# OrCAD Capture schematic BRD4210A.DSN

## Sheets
1 WSTK Connectors & Board ID: size A3; title: xG23B 868-915 MHz 20 dBm Radio Board; rev: A00; company: Silicon Labs; note: BRD4210A
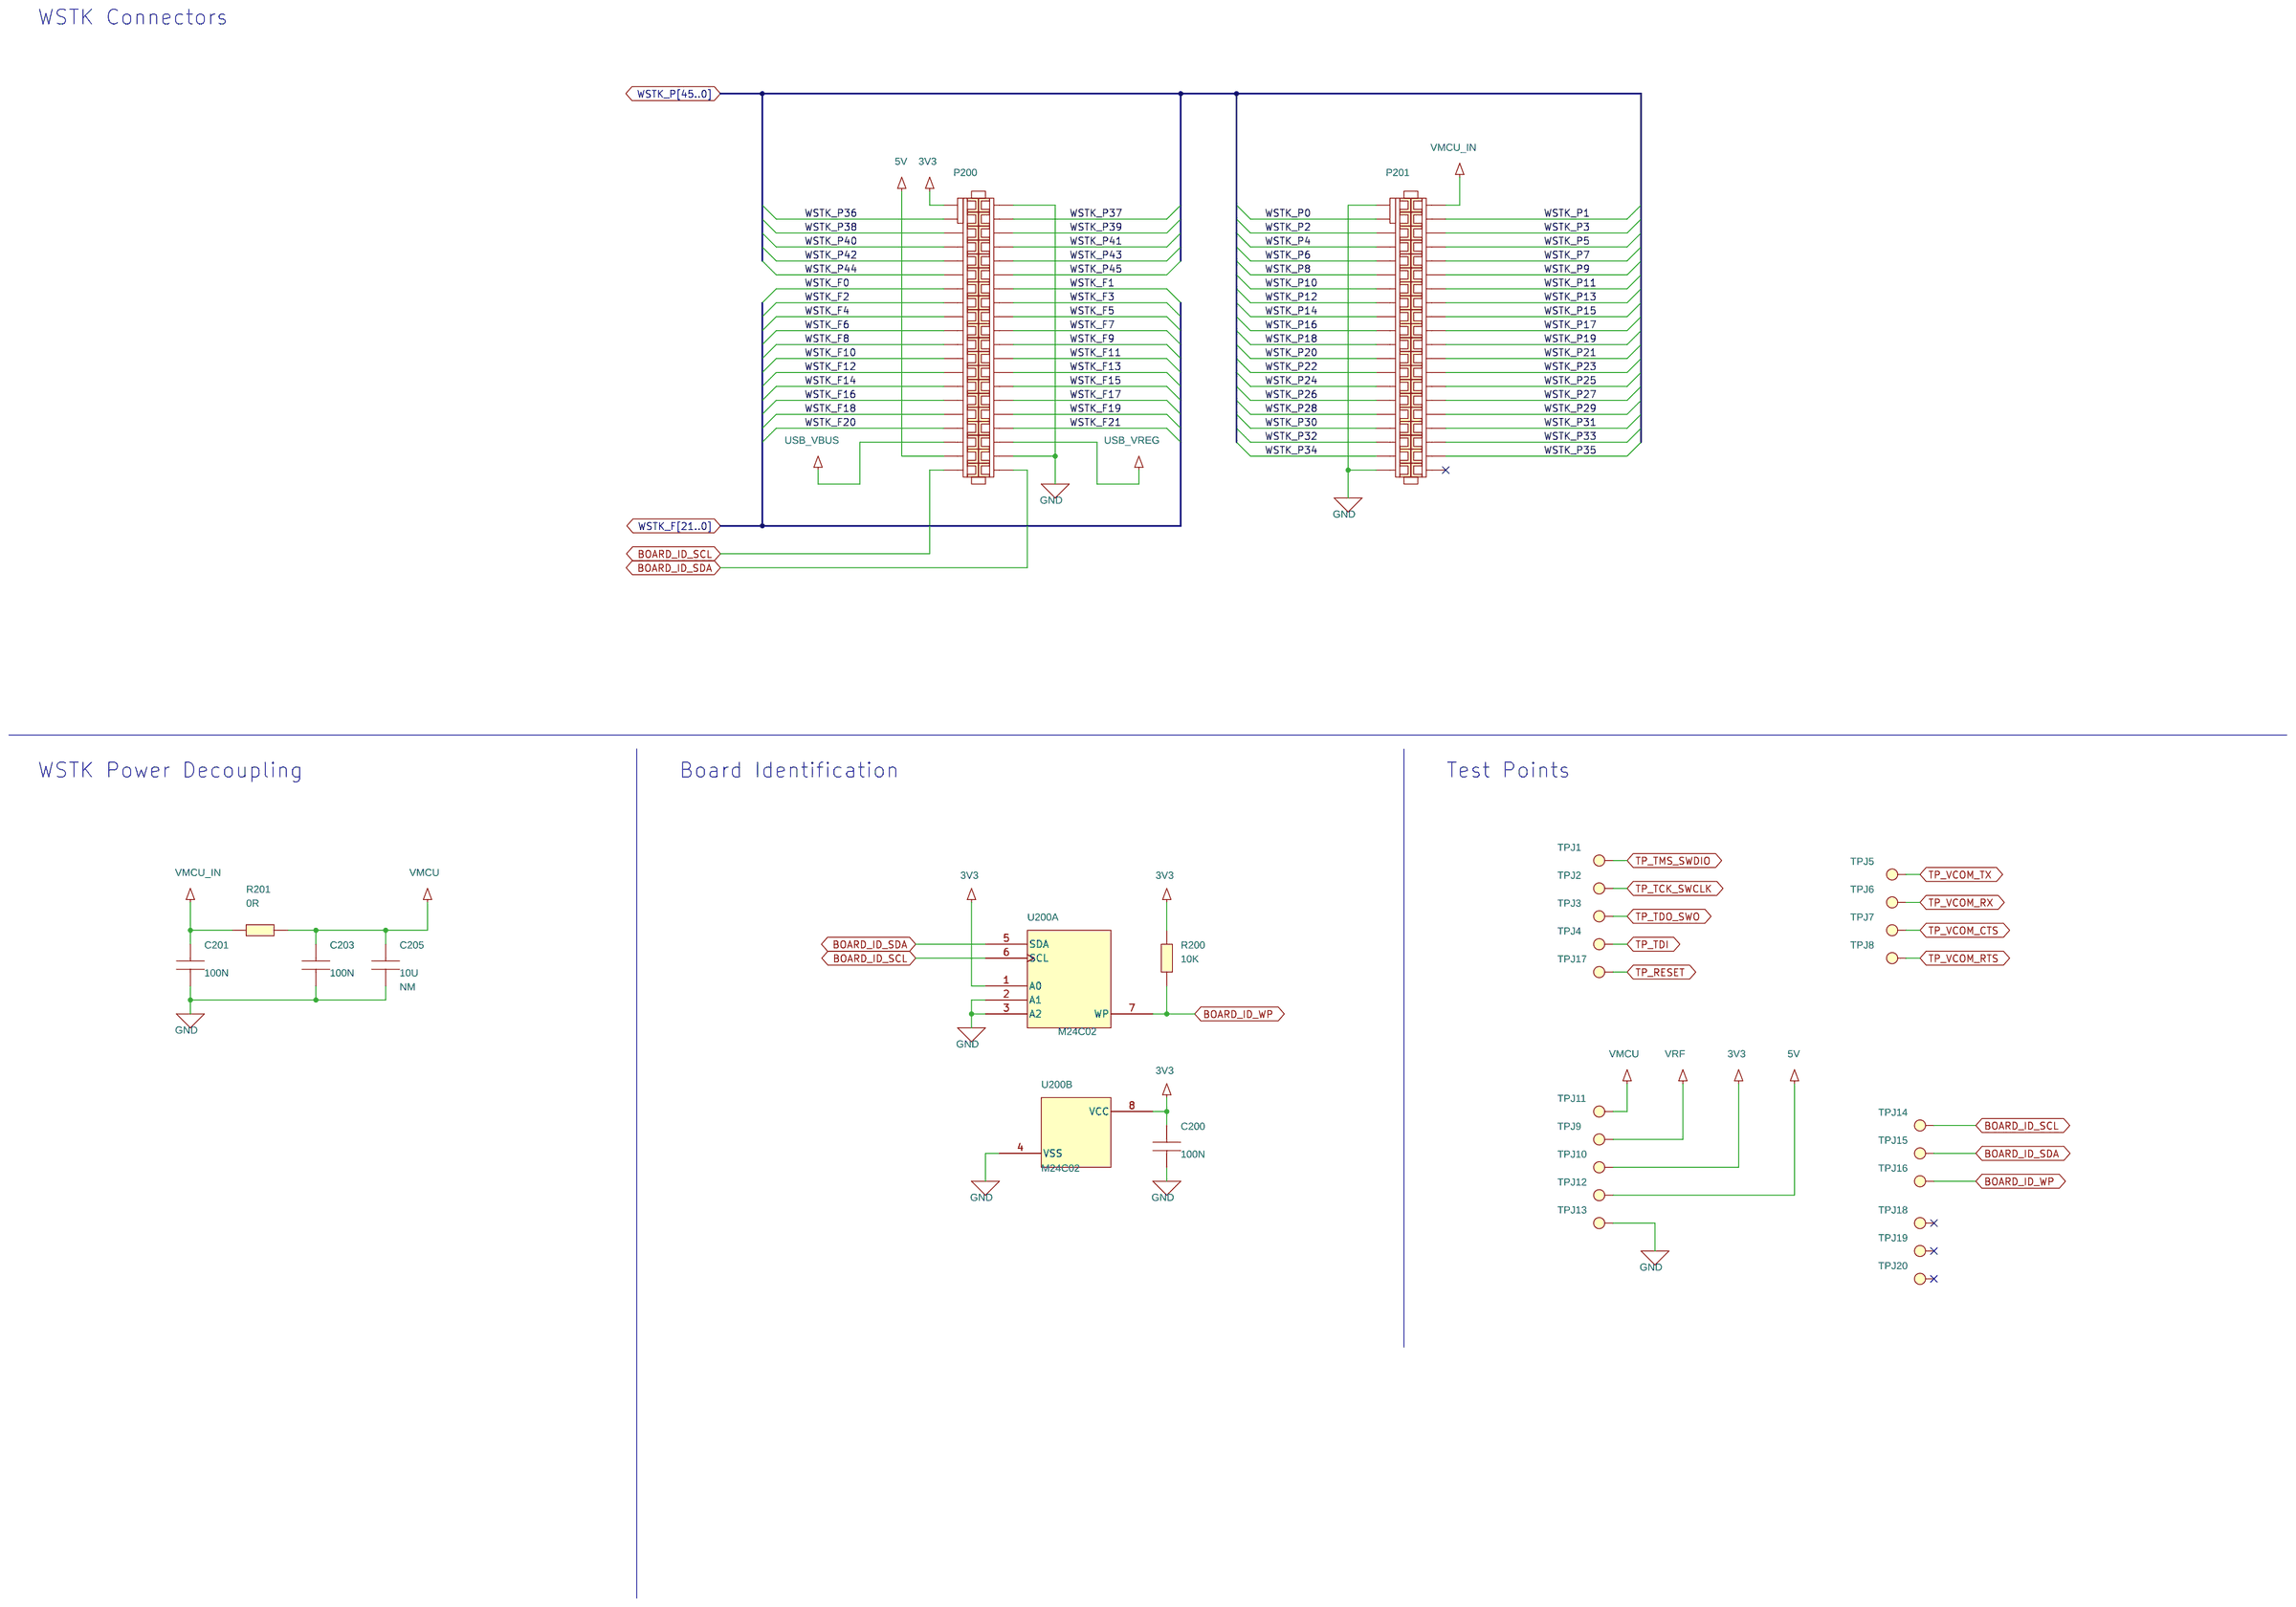
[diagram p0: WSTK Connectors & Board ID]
2 02: RF & Power: size A3
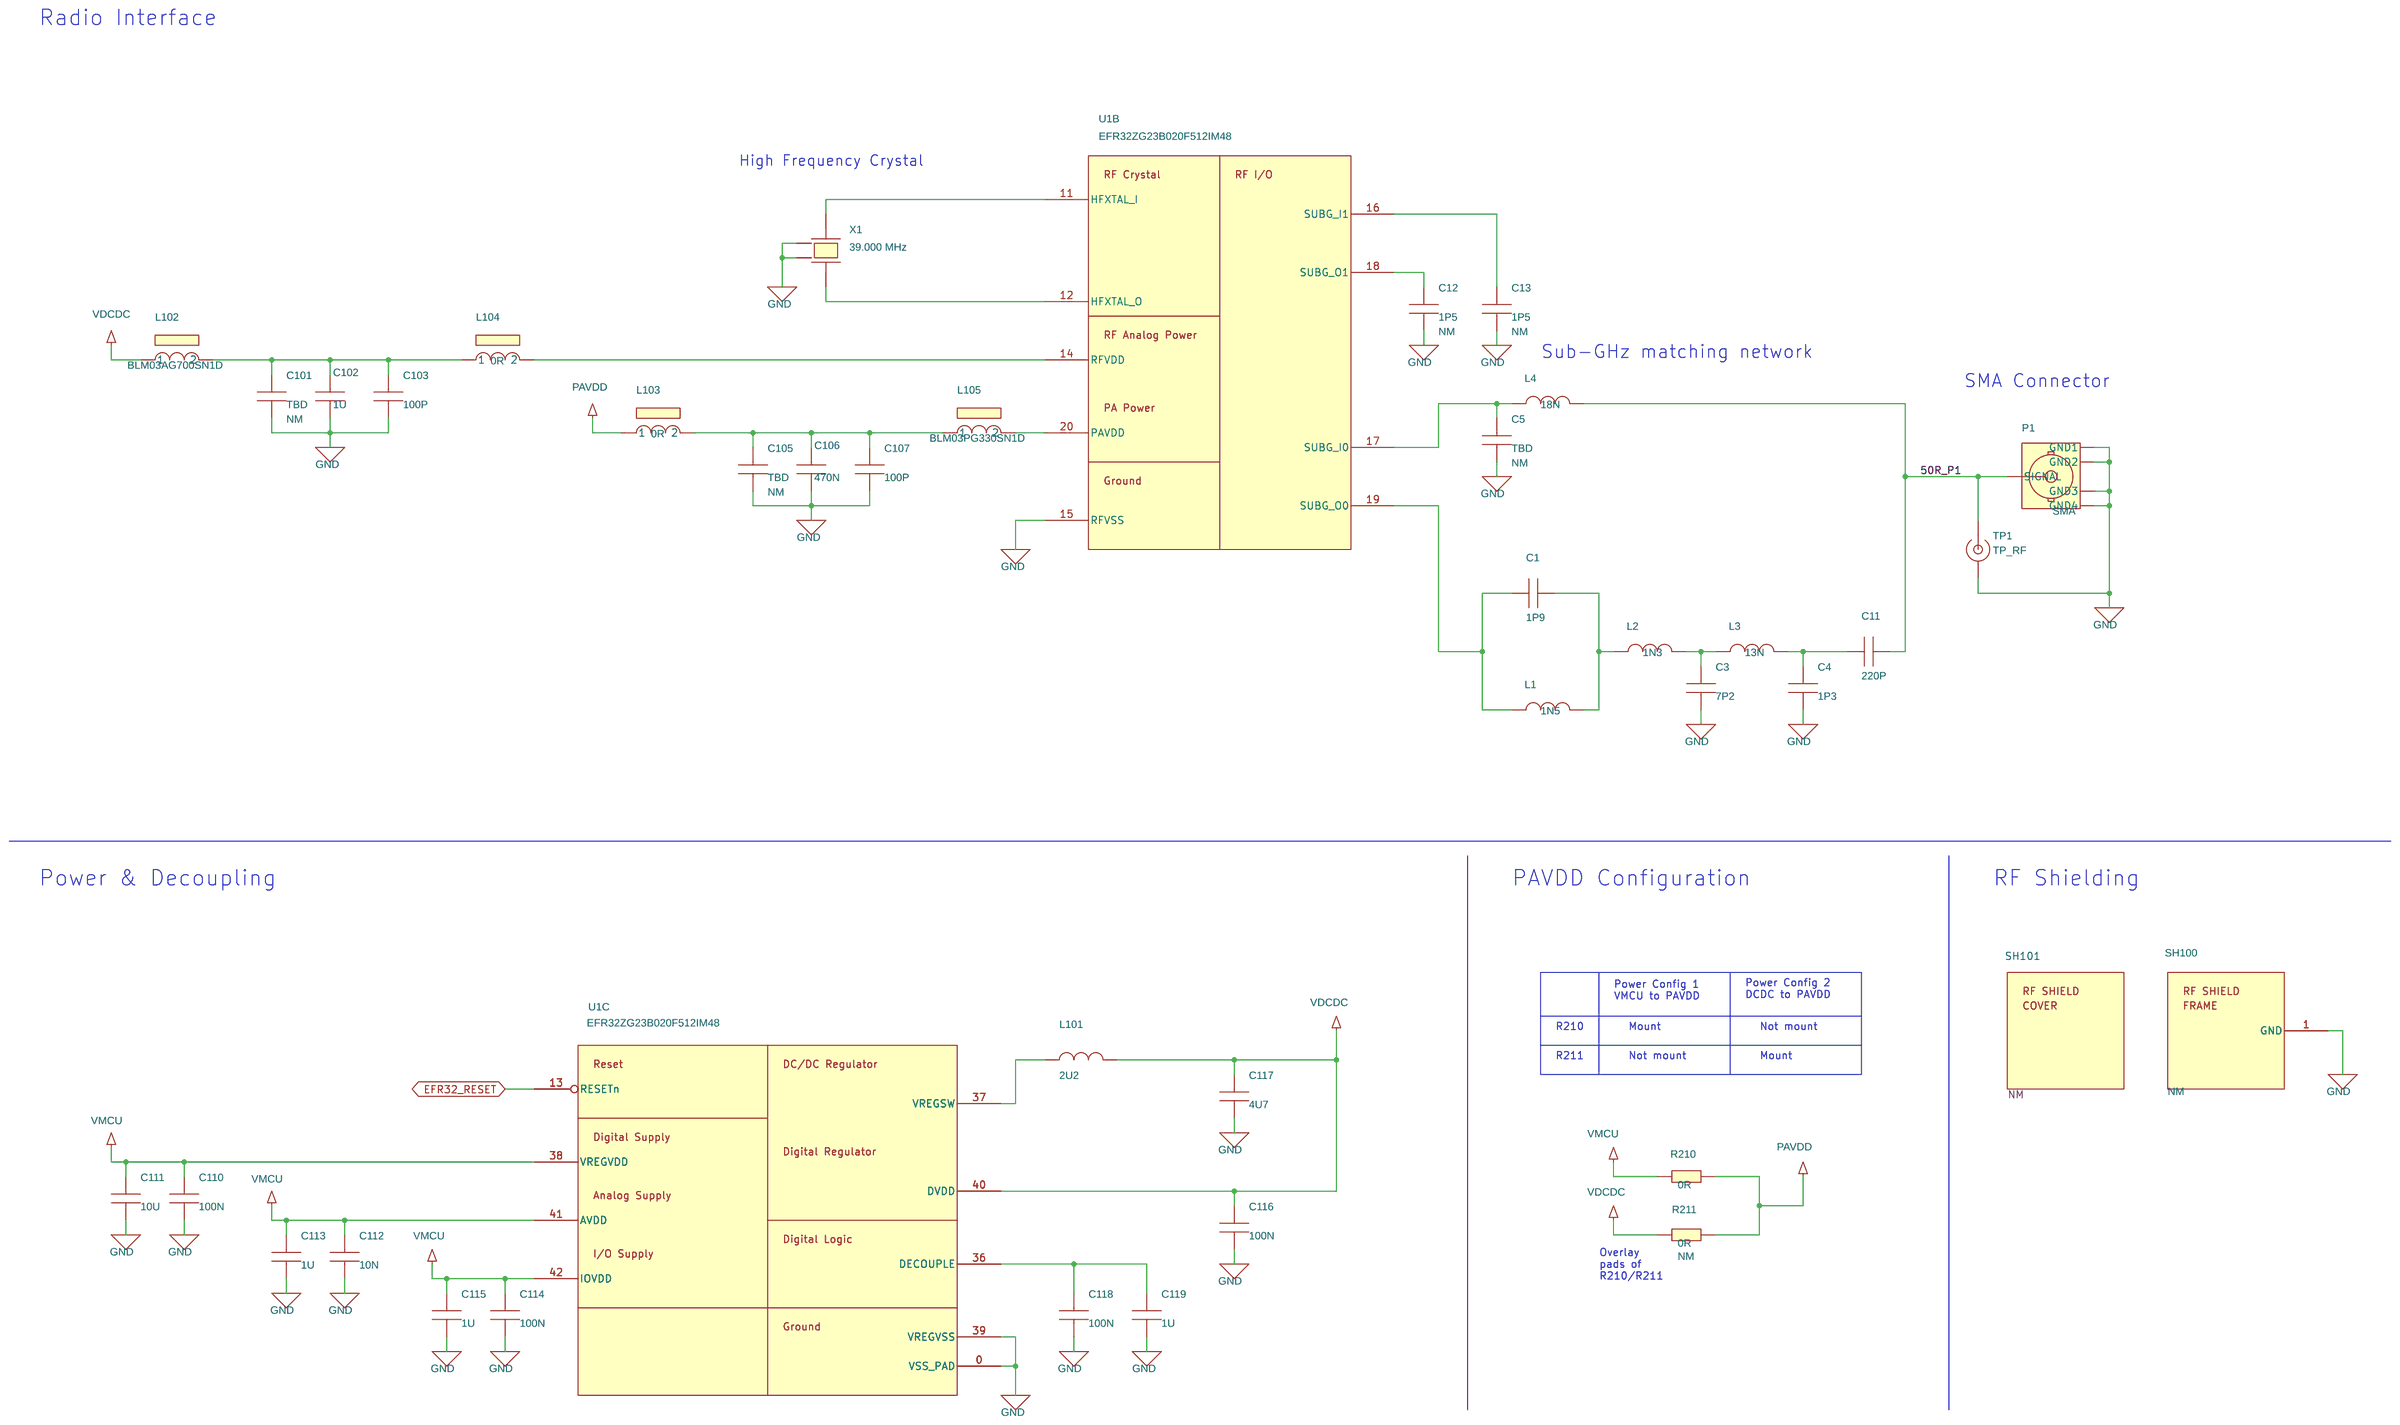
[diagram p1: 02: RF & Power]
3 01: Title Page
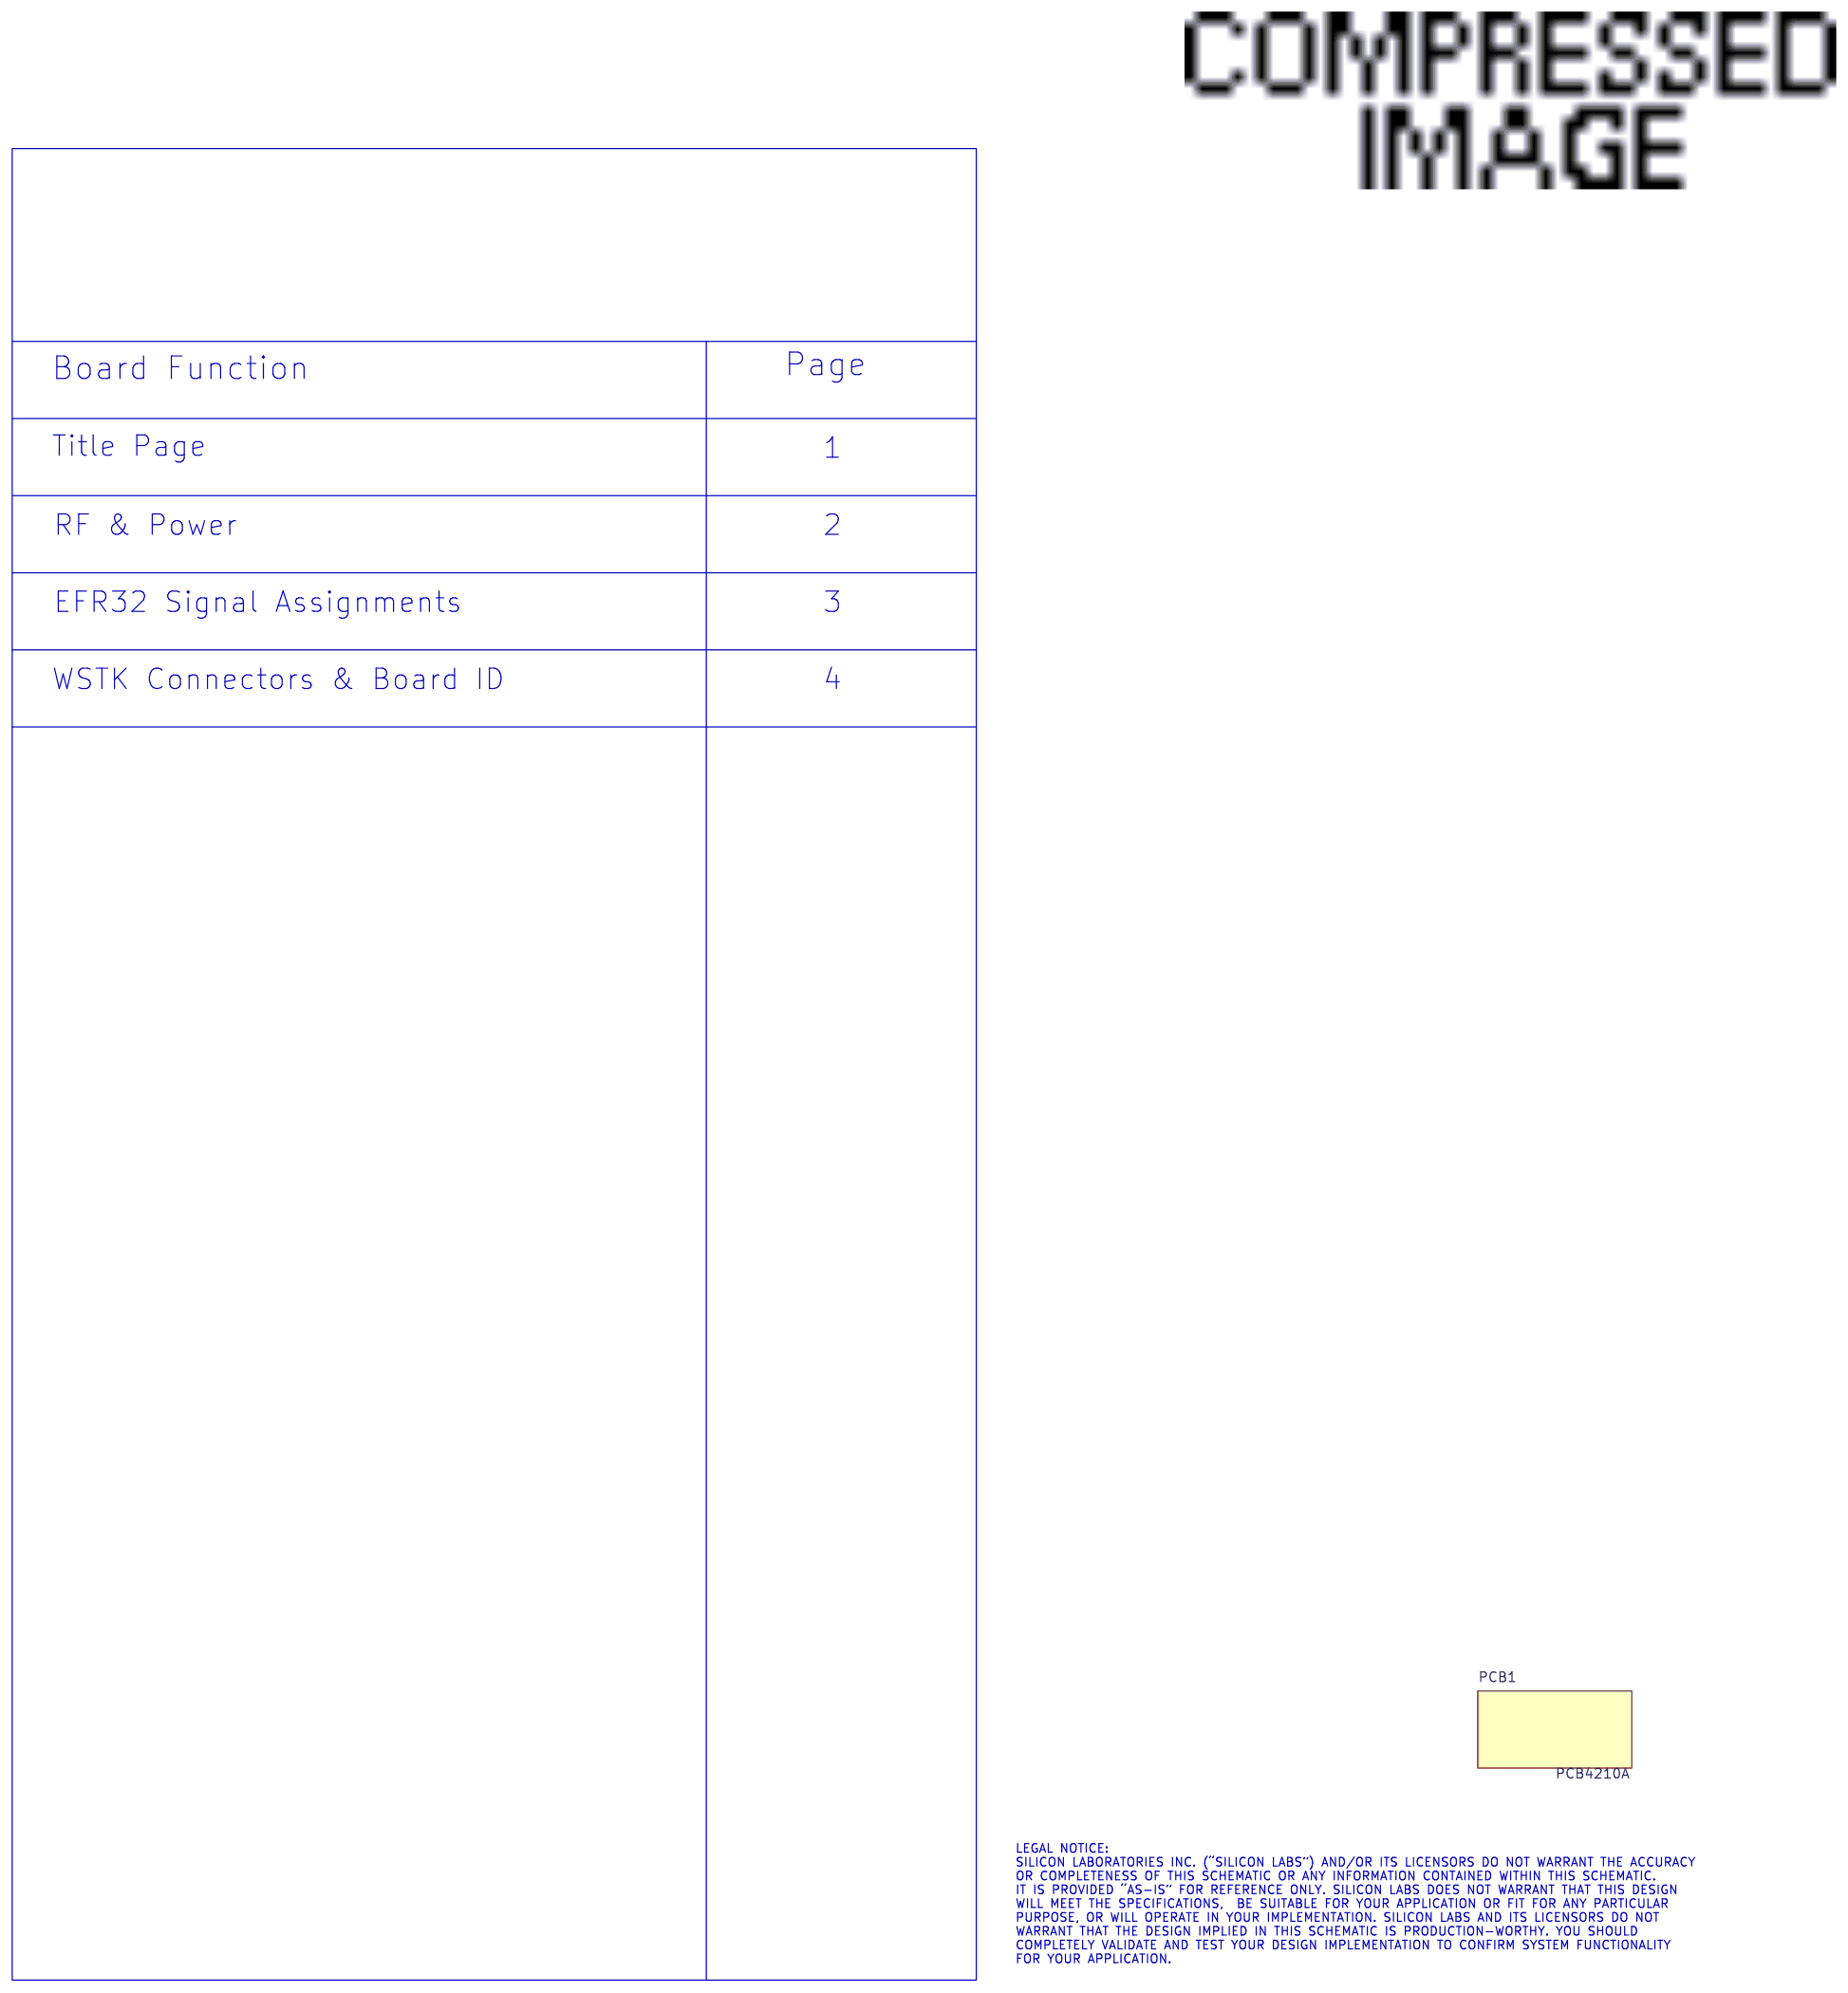
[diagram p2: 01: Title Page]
4 03: EFR32 Signal Assignments: size A3
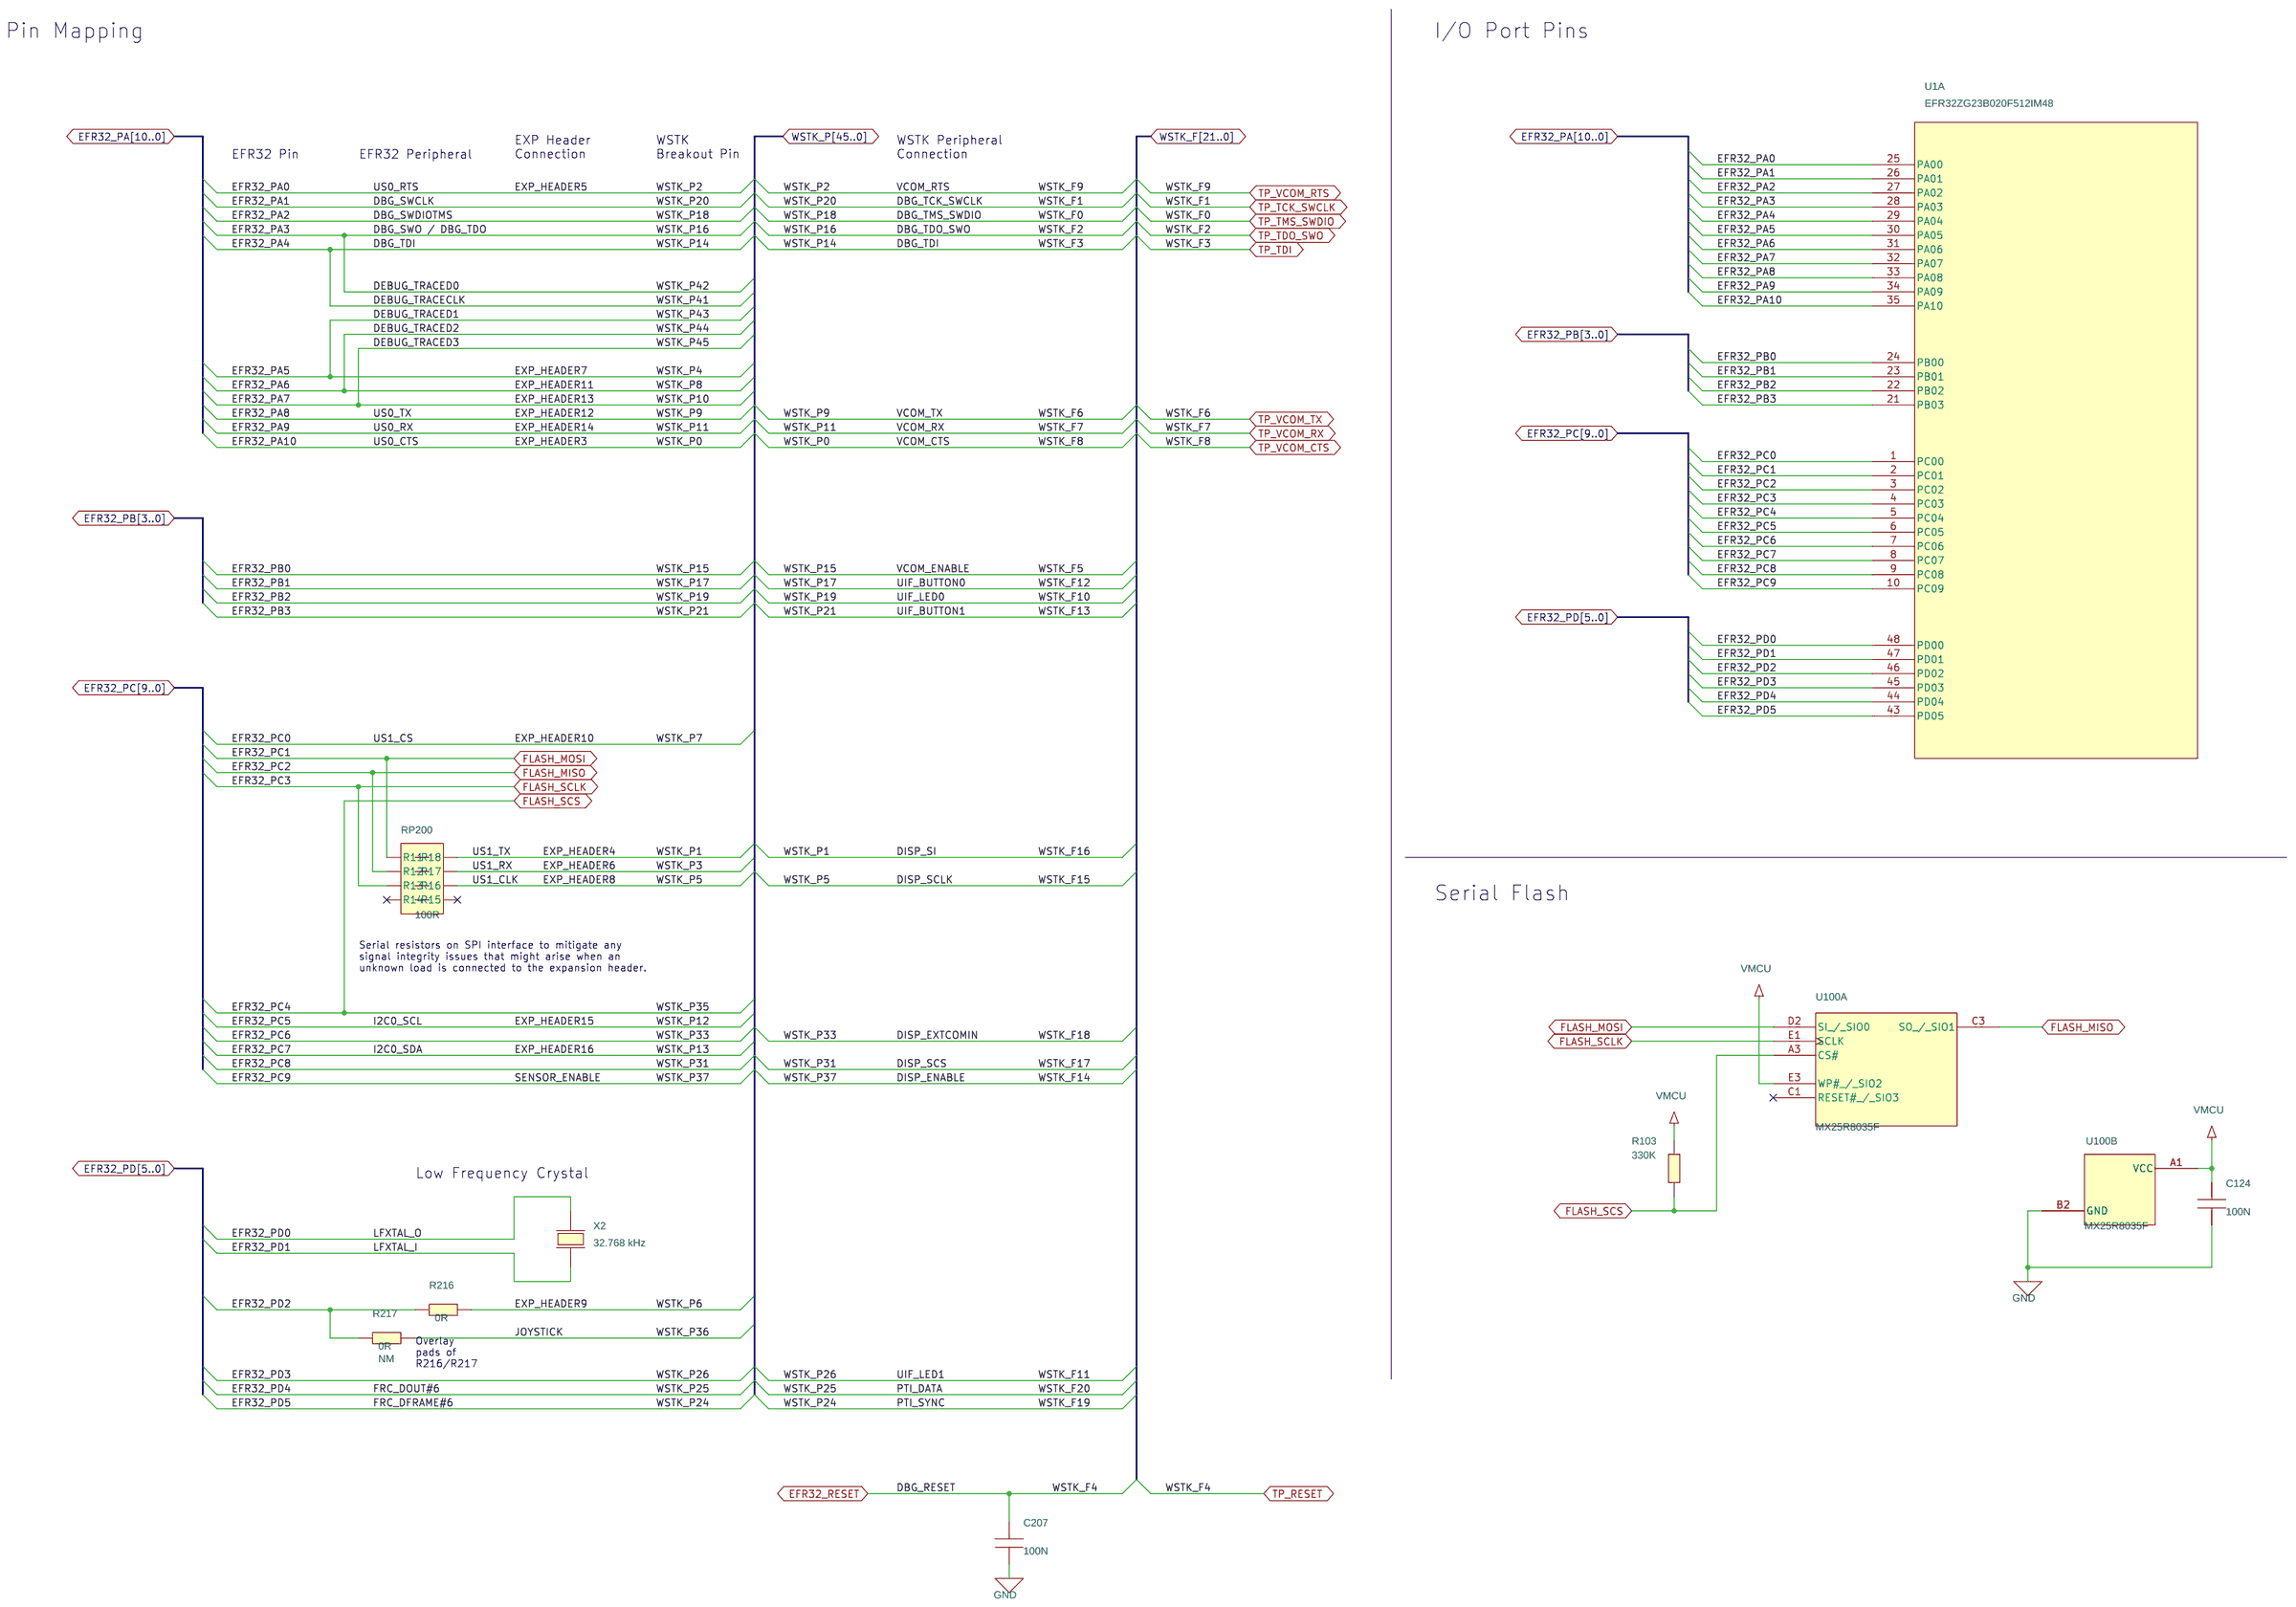
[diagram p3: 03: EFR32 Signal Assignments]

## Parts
sheet 01: Title Page
PCB1  PCB4210A  [N/A]
sheet 02: RF & Power
C1  1P9  [C0201_L]
C3  7P2  [C0201_L]
C4  1P3  [C0201_L]
C5  TBD  [C0201_L]
C11  220P  [C0201_L]
C12  1P5  [C0201_L]
C13  1P5  [C0201_L]
C101  TBD  [C0201_L]
C102  1U  [C0402_L]
C103  100P  [C0201_L]
C105  TBD  [C0201_L]
C106  470N  [C0402_L]
C107  100P  [C0201_L]
C110  100N  [C0201_L]
C111  10U  [C0603_L]
C112  10N  [C0201_L]
C113  1U  [C0402_L]
C114  100N  [C0201_L]
C115  1U  [C0402_L]
C116  100N  [C0201_L]
C117  4U7  [C0603_L]
C118  100N  [C0201_L]
C119  1U  [C0402_L]
L1  1N5  [COIL_0201_L]
L2  1N3  [COIL_0201_L]
L3  13N  [COIL_0201_L]
L4  18N  [COIL_0201_L]
L101  2U2  [COIL_1008_L]
L102  BLM03AG700SN1D  [COIL_MUR_BLM03_0201]
L103  0R  [COIL_MUR_BLM03_0201]
L104  0R  [COIL_MUR_BLM03_0201]
L105  BLM03PG330SN1D  [COIL_MUR_BLM03_0201]
P1  SMA  [TE_SMA_1814832_TH_VER]
R210  0R  [R0402_L]
R211  0R  [R0402_L]
SH100  RF_SHIELD_FRAME_36103205S  [Shield_21x21mm]
SH101  RF_SHIELD_COVER_36003200S
TP1  TP_RF  [TP_INGUN_50_OHM_CLOSED openvia]
X1  39.000 MHz  [KDS_DSX211SH_2016]
sheet 03: EFR32 Signal Assignments
C124  100N  [C0201_L]
C207  100N  [C0201_L]
R103  330K  [R0201_L]
R216  0R  [R0402_L]
R217  0R  [R0402_L]
RP200  100R  [RES_MNR04-8]
U1  EFR32ZG23B020F512IM48  [QFN48_M040_6.0X6.0_EP_SL]  (sections A,B,C)
U100  MX25R8035F  [BGA8_M040_1.24x1.75_WLCSP]  (sections A,B)
X2  32.768 kHz  [X_MCS_CM8V-T1A]
sheet WSTK Connectors & Board ID
C200  100N  [C0201_L]
C201  100N  [C0201_L]
C203  100N  [C0201_L]
C205  10U  [C0805_L]
P200  SOCKET_WCON_2X20_1.27MM_SMD  [SAM_SFC-120-T2-D-A-2X20_SNUM]
P201  SOCKET_WCON_2X20_1.27MM_SMD  [SAM_SFC-120-T2-D-A-2X20_SNUM]
R200  10K  [R0201_L]
R201  0R  [R0402_L]
TPJ1  TPJ_SMD  [TP_1.0_SMD]
TPJ2  TPJ_SMD  [TP_1.0_SMD]
TPJ3  TPJ_SMD  [TP_1.0_SMD]
TPJ4  TPJ_SMD  [TP_1.0_SMD]
TPJ5  TPJ_SMD  [TP_1.0_SMD]
TPJ6  TPJ_SMD  [TP_1.0_SMD]
TPJ7  TPJ_SMD  [TP_1.0_SMD]
TPJ8  TPJ_SMD  [TP_1.0_SMD]
TPJ9  TPJ_SMD  [TP_1.0_SMD]
TPJ10  TPJ_SMD  [TP_1.0_SMD]
TPJ11  TPJ_SMD  [TP_1.0_SMD]
TPJ12  TPJ_SMD  [TP_1.0_SMD]
TPJ13  TPJ_SMD  [TP_1.0_SMD]
TPJ14  TPJ_SMD  [TP_1.0_SMD]
TPJ15  TPJ_SMD  [TP_1.0_SMD]
TPJ16  TPJ_SMD  [TP_1.0_SMD]
TPJ17  TPJ_SMD  [TP_1.0_SMD]
TPJ18  TPJ_SMD  [TP_1.0_SMD]
TPJ19  TPJ_SMD  [TP_1.0_SMD]
TPJ20  TPJ_SMD  [TP_1.0_SMD]
U200  M24C02  [TDFN8_M050_2.0X3.0_EP]  (sections A,B)

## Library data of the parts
PCB1 = PCB: Mfg #: PCB4210A Rev. A01; Price_1K: 1.25
C1 = C0201: Mfg: Murata; Mfg #: GRM0335C1H1R9BA01D; Technology: C0G; Tolerance: ±0.1pF
C3 = C0201: Mfg: Murata; Mfg #: GRM0335C1H7R2BA01D; Technology: C0G; Tolerance: ±0.1pF
C4 = C0201: Mfg: Murata; Mfg #: GRM0335C1H1R3BA01D; Technology: C0G; Tolerance: ±0.1pF
C5 = C0201: Not Mounted: NM
C11 = C0201: Mfg: Murata; Mfg #: GRM0335C1H221GA01D; Technology: C0G; Tolerance: ±2%
C12 C13 = C0201: Mfg: Murata; Mfg #: GRM0335C1E1R5WA01D; Not Mounted: NM; Technology: C0G; Tolerance: ±0.05pF
C101 C105 = C0201: Not Mounted: NM; Rating: 50V; Technology: C0G; Tolerance: +/-0.05P
C102 C113 C115 C119 = C0402: Rating: 6.3V; Technology: X7R; Tolerance: 10%
C103 C107 = C0201: Rating: 25V; Technology: C0G; Tolerance: 5%
C106 = C0402: Rating: 10V; Technology: X7R; Tolerance: 10%
C110 C114 C116 C118 C124 C200 C201 C203 C207 = C0201: Rating: 16V; Technology: X7S; Tolerance: 20%
C111 = C0603: Rating: 25V; Technology: X5R; Tolerance: 10%
C112 = C0201: Rating: 16V; Technology: X7S; Tolerance: 10%
C117 = C0603: Rating: 6.3V; Technology: X7R; Tolerance: 10%
L1 = L0201: Mfg: Murata; Mfg #: LQP03HQ1N5W02D; Tolerance: ±0.05nH
L2 = L0201: Mfg: Murata; Mfg #: LQP03HQ1N3W02D; Tolerance: ±0.05nH
L3 = L0201: Mfg: Murata; Mfg #: LQP03HQ13NH02D; Tolerance: ±3%
L4 = L0201: Mfg: Murata; Mfg #: LQP03HQ18NH02D; Tolerance: ±3%
L101 = L1008: Mfg: Murata; Mfg #: DFE2HCAH2R2MJ0L; Tolerance: +/-20%
L102 = BLM03AX_1
L103 = BLM03AX_3
L104 = BLM03AX_2
L105 = BLM03AX
P1 = SMA_TH_WELLSHOW
R210 R216 = R0402
R211 R217 = R0402: Not Mounted: NM
SH100 = RF_SHIELD_FRAME_36103205S: Not Mounted: NM
SH101 = RF_SHIELD_COVER_36003200S: Not Mounted: NM
TP1 = TP_RF
X1 = DSX211SH: Mfg: Tai-Saw; Mfg #: TZ3541C; Price_1K: 0.512
R103 R200 = R0201
RP200 = MNR04M0APJ101
U1 = EFR32xG23_QFN48: Mfg #: EFR32ZG23B020F512IM48-BR
U100 = MX25R8035
X2 = CM8V-T1A: Mfg: Micro Crystal AG; Mfg #: CM8V-T1A-32.768KHZ-7PF-20PPM-TA-QC
C205 = CAPACITOR: Not Mounted: NM; Technology: X5R
P200 P201 = SOCKET_WCON_2X20_1.27MM_SMD: Mfg #: 2344-220MS3CUNR6
R201 = RESISTOR
TPJ1-TPJ20 = TPJ_SMD
U200 = M24C02: CONTEC Footprint: MSOP8_M065_W3.0; Mfg: ST Microelectronics; Mfg #: M24C02-FMC6TG; Price_1K: 0.06

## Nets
3V3: C200.1 P200.1 R200.2 TPJ10.1(TP) U200.1(A0) U200.8(VCC)
5V: P200.37 TPJ12.1(TP)
GND: C3.2 C4.2 C5.2 C12.2 C13.2 C101.2 C102.2 C103.2 C105.2 C106.2 C107.2 C110.2 C111.2 C112.2 C113.2 C114.2 C115.2 C116.2 C117.2 C118.2 C119.2 C124.2 C200.2 C201.2 C203.2 C205.2 C207.2 P1.2(GND1) P1.3(GND2) P1.4(GND3) P1.5(GND4) P200.2 P200.38 P201.1 P201.39 SH100.1(GND) TP1.2(GND) TPJ13.1(TP) U1.0(VSS_PAD) U1.15(RFVSS) U1.39(VREGVSS) U100.B2(GND) U200.2(A1) U200.3(A2) U200.4(VSS) X1.2 X1.4
50R_P1: C11.2 L4.2 P1.1(SIGNAL) TP1.1(RF)
BOARD_ID_SCL: P200.39 TPJ14.1(TP) U200.6(SCL)
BOARD_ID_SDA: P200.40 TPJ15.1(TP) U200.5(SDA)
BOARD_ID_WP: R200.1 TPJ16.1(TP) U200.7(WP)
EFR32_PA0: P200.22 P201.5 TPJ8.1(TP) U1.25(PA00)
EFR32_PA1: P200.14 P201.23 TPJ2.1(TP) U1.26(PA01)
EFR32_PA2: P200.13 P201.21 TPJ1.1(TP) U1.27(PA02)
EFR32_PA3: P200.9 P200.15 P201.19 TPJ3.1(TP) U1.28(PA03)
EFR32_PA4: P200.8 P200.16 P201.17 TPJ4.1(TP) U1.29(PA04)
EFR32_PA5: P200.10 P201.7 U1.30(PA05)
EFR32_PA6: P200.11 P201.11 U1.31(PA06)
EFR32_PA7: P200.12 P201.13 U1.32(PA07)
EFR32_PA8: P200.19 P201.12 TPJ5.1(TP) U1.33(PA08)
EFR32_PA9: P200.20 P201.14 TPJ6.1(TP) U1.34(PA09)
EFR32_PA10: P200.21 P201.3 TPJ7.1(TP) U1.35(PA10)
EFR32_PB0: P200.18 P201.18 U1.24(PB00)
EFR32_PB1: P200.25 P201.20 U1.23(PB01)
EFR32_PB2: P200.23 P201.22 U1.22(PB02)
EFR32_PB3: P200.26 P201.24 U1.21(PB03)
EFR32_PC0: P201.10 U1.1(PC00)
EFR32_PC1: RP200.1(R11) U1.2(PC01) U100.D2(SI_/_SIO0)
EFR32_PC2: RP200.2(R12) U1.3(PC02) U100.C3(SO_/_SIO1)
EFR32_PC3: RP200.3(R13) U1.4(PC03) U100.E1(SCLK)
EFR32_PC4: P201.38 R103.1 U1.5(PC04) U100.A3(CS#)
EFR32_PC5: P201.15 U1.6(PC05)
EFR32_PC6: P200.31 P201.36 U1.7(PC06)
EFR32_PC7: P201.16 U1.8(PC07)
EFR32_PC8: P200.30 P201.34 U1.9(PC08)
EFR32_PC9: P200.4 P200.27 U1.10(PC09)
EFR32_PD0: U1.48(PD00) X2.1
EFR32_PD1: U1.47(PD01) X2.2
EFR32_PD2: R216.1 R217.1 U1.46(PD02)
EFR32_PD3: P200.24 P201.29 U1.45(PD03)
EFR32_PD4: P200.33 P201.28 U1.44(PD04)
EFR32_PD5: P200.32 P201.27 U1.43(PD05)
EFR32_RESET: C207.1 P200.17 TPJ17.1(TP) U1.13(RESETn)
PAVDD: L103.1 R210.1 R211.2
USB_VBUS: P200.35
USB_VREG: P200.36
VDCDC: C116.1 C117.1 L101.2 L102.1 R211.1 U1.40(DVDD)
VMCU: C110.1 C111.1 C112.1 C113.1 C114.1 C115.1 C124.1 C203.1 C205.1 R103.2 R201.2 R210.2 TPJ11.1(TP) U1.38(VREGVDD) U1.41(AVDD) U1.42(IOVDD) U100.A1(VCC) U100.E3(WP#_/_SIO2)
VMCU_IN: C201.1 P201.2 R201.1
VRF: TPJ9.1(TP)
WSTK_F15: P200.28 P201.8 RP200.6(R16)
WSTK_F16: P200.29 P201.4 RP200.8(R18)
WSTK_F21: P200.34
WSTK_P3: P201.6 RP200.7(R17)
WSTK_P6: P201.9 R216.2
WSTK_P22: P201.25
WSTK_P23: P201.26
WSTK_P27: P201.30
WSTK_P28: P201.31
WSTK_P29: P201.32
WSTK_P30: P201.33
WSTK_P32: P201.35
WSTK_P34: P201.37
WSTK_P36: P200.3 R217.2
WSTK_P38: P200.5
WSTK_P39: P200.6
WSTK_P40: P200.7
N17556303: C101.1 C102.1 C103.1 L102.2 L104.1
N17556352: C1.1 L1.1 U1.19(SUBG_O0)
N17556358: C1.2 L1.2 L2.1
N17556449: L104.2 U1.14(RFVDD)
N17556453: L105.2 U1.20(PAVDD)
N17556723: C118.1 C119.1 U1.36(DECOUPLE)
N17556727: L101.1 U1.37(VREGSW)
N17556799: C5.1 L4.1 U1.17(SUBG_I0)
N17556841: C3.1 L2.2 L3.1
N17556911: C4.1 C11.1 L3.2
N17557012: C13.1 U1.16(SUBG_I1)
N17557016: C12.1 U1.18(SUBG_O1)
N17557090: C105.1 C106.1 C107.1 L103.2 L105.1
N17557115: U1.11(HFXTAL_I) X1.3
N17557130: U1.12(HFXTAL_O) X1.1

Not connected (* = marked no-connect by the designer): P201 40*; RP200 4(R14)* 5(R15)*; TPJ18 1(TP)*; TPJ19 1(TP)*; TPJ20 1(TP)*; U100 C1(RESET#_/_SIO3)*

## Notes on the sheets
sheet 1
- WSTK Connectors
- WSTK Power Decoupling
- Board Identification
- Test Points
sheet 2
- Radio Interface
- High Frequency Crystal
- Sub-GHz matching network
- SMA Connector
- Power & Decoupling
- PAVDD Configuration
- RF Shielding
- Power Config 1
  VMCU to PAVDD
- Power Config 2
  DCDC to PAVDD
- R210
- Mount
- Not mount
- R211
- Not mount
- Mount
- Overlay
  pads of
  R210/R211
sheet 3
- Board Function
- Page
- Title Page
- 1
- RF & Power
- 2
- EFR32 Signal Assignments
- 3
- WSTK Connectors & Board ID
- 4
- LEGAL NOTICE:
  SILICON LABORATORIES INC. (“SILICON LABS”) AND/OR ITS LICENSORS DO NOT WARRANT THE ACCURACY
  OR COMPLETENESS OF THIS SCHEMATIC OR ANY INFORMATION CONTAINED WITHIN THIS SCHEMATIC.
  IT IS PROVIDED “AS-IS” FOR REFERENCE ONLY. SILICON LABS DOES NOT WARRANT THAT THIS DESIGN
  WILL MEET THE SPECIFICATIONS,  BE SUITABLE FOR YOUR APPLICATION OR FIT FOR ANY PARTICULAR
  PURPOSE, OR WILL OPERATE IN YOUR IMPLEMENTATION. SILICON LABS AND ITS LICENSORS DO NOT
  WARRANT THAT THE DESIGN IMPLIED IN THIS SCHEMATIC IS PRODUCTION-WORTHY. YOU SHOULD
  COMPLETELY VALIDATE AND TEST YOUR DESIGN IMPLEMENTATION TO CONFIRM SYSTEM FUNCTIONALITY
  FOR YOUR APPLICATION.
sheet 4
- Pin Mapping
- I/O Port Pins
- EFR32 Pin
- EFR32 Peripheral
- EXP Header
  Connection
- WSTK
  Breakout Pin
- WSTK Peripheral
  Connection
- Serial Flash
- Serial resistors on SPI interface to mitigate any
  signal integrity issues that might arise when an
  unknown load is connected to the expansion header.
- Low Frequency Crystal
- Overlay
  pads of
  R216/R217
